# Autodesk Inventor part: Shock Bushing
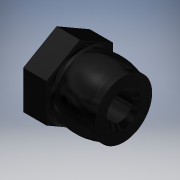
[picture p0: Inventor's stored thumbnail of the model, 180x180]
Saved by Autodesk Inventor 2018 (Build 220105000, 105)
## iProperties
Shininess: 50.0
Compacted: True
Length Units: 11272
Angle Units: 11279
Time Units: 11290
Mass Units: 11286
Length Display Precision: 4
Angle Display Precision: 2
Company: Autodesk
Created: 2000-07
Part Number: Shock Bushing
Project: Inventor Samples
Document SubType Name: Modeling
Designer: Autodesk, Inc.
Density: 1.13 g/cm^3
Mass: 0.177954 g
Surface Area: 2.27867 cm^2
Volume: 0.157481 cm^3
Material: Nylon-6/6
Appearance: Glossy - Black
Density: 0.0
Volumn: 0.0
Area: 0.0
PropertySet Name: Model Information
Control State: 0
Master: False
Checked Out: False
Author: Autodesk, Inc.
Revision Number: A
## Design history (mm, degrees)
node "Revolution1" dims "d9" = 90 deg
  sketch "Sketch3"
    geometry: L1 (-7.537, 0.965)-(-13.29, 0.965); L2 (-13.29, 0.965)-(-13.29, 2.895); L3 (-13.29, 2.895)-(-11.068, 2.895); L4 (-11.068, 2.895)-(-11.068, 2.452); L5 (-7.537, 0.965)-(-7.537, 2.452); L6 (-13.29, -0.28)-(-7.606, -0.28); A1 r 5.08 centre (-9.303, -2.312) between (-7.537, 2.452) and (-11.068, 2.452)
    constraints: 12 end point, 3 parallel, 2 perpendicular, 2 point on circle, 1 centre point, 1 horizontal, 1 horizontal alignment, 1 point on line, 1 other
    dimensions: "d1" = 2.4892 diameter of L1 L6; "d2" = 6.35 diameter of L3 L6; "d3" = 2.2225 distance of L2.end L3.end; "d4" = 6.096 dimension on A1 L6; "d7" = 3.9878 distance from line of A1.centre L2; "d10" = 5.08 radius of A1
node "Extrusion1" dims "d14" = 25.4, "d15" = 0
  sketch "Sketch4"
    geometry: L1 (-3.175, -1.833)-(-3.175, 1.833); L2 (-3.175, 1.833)-(0, 3.666); L3 (0, 3.666)-(3.175, 1.833); L4 (3.175, 1.833)-(3.175, -1.833); L5 (3.175, -1.833)-(0, -3.666); L6 (0, -3.666)-(-3.175, -1.833); C1 r 3.175 at (0, 0) reference
    constraints: 12 end point, 6 tangent, 3 parallel, 2 equal length, 1 vertical
node "Extrusion2" dims "d17" = 0.635, "d18" = 0
  sketch "Sketch5"
    geometry: C1 r 1.245 at (0, 0) reference; C2 r 2.731 at (0, 0) reference
node "Fillet1" dims "d16" = 0.381
node "Chamfer1" dims "d12" = 0.381, "d13" = 0.381, "d19" = 45 deg
body "Solid1"
other parameters: "d11" = 6.0706 (derived), "d20" = 0
